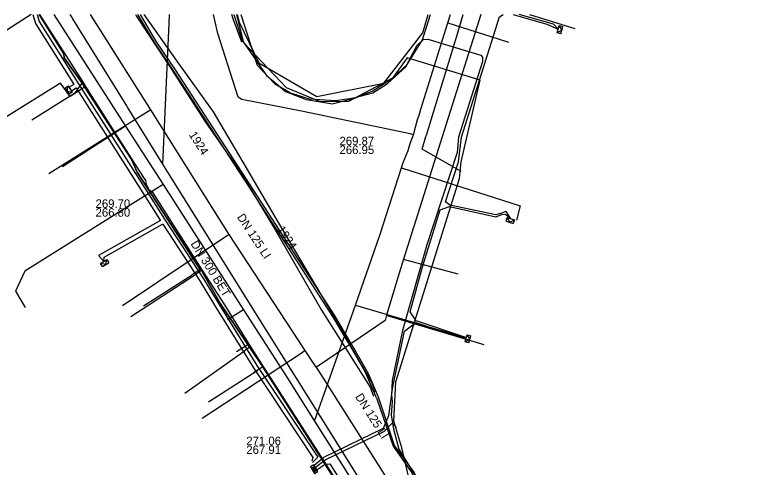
# Model space of a CAD drawing. Extents: x -600391 to -599491, y -1160176 to -1159402.
# Drawn here: x -600036.7 to -599967.6, y -1159444.5 to -1159401.8 of the extents above; entities that cross this region are included whole.
import ezdxf

# ---------------------------------------------------------------- set-up
doc = ezdxf.new("R2010")
doc.units = 0
for name, color, linetype in [('28', 7, 'Continuous'), ('31', 7, 'Continuous'), ('CETIN_linie', 7, 'Continuous'), ('UPC_ok_linie', 7, 'Continuous'), ('Vrstva 12', 7, 'Continuous'), ('Vrstva 13', 7, 'Continuous'), ('Vrstva 15', 7, 'Continuous'), ('Vrstva 16', 7, 'Continuous'), ('Vrstva 42', 7, 'Continuous'), ('Vrstva 43', 7, 'Continuous'), ('Vrstva 44', 7, 'Continuous'), ('Vrstva 55', 7, 'Continuous'), ('Vrstva 9', 7, 'Continuous')]:
    doc.layers.add(name, color=color, linetype=linetype)

# ---------------------------------------------------------------- blocks, each defined once
blk = doc.blocks.new('NN630')
at = {"layer": '31'}
for points in [[(0, -0.7), (-0.7, 0)], [(-0.7, -0.7), (-0.7, 0), (0.7, 0), (0.7, -0.7)], [(-0.7, -0.7), (0.7, -0.7)], [(0, -0.7), (0.7, 0)]]:
    blk.add_lwpolyline(points, dxfattribs=at)
blk = doc.blocks.new('NN620')
at = {"layer": '28'}
for points in [[(0.75, 0), (-0.75, 0)], [(-0.75, 0), (-0.75, -0.75)], [(0.75, -0.75), (0.75, 0)], [(-0.75, -0.75), (0.75, -0.75)], [(0.37, -0.18), (-0.38, -0.18)], [(-0.38, -0.18), (-0.38, -0.56)], [(-0.38, -0.56), (0.37, -0.56)], [(0.32, -0.23), (-0.33, -0.23)], [(-0.33, -0.23), (-0.33, -0.51)], [(-0.33, -0.51), (0.32, -0.51)], [(0.27, -0.27), (-0.28, -0.27)], [(-0.28, -0.27), (-0.28, -0.46)], [(-0.28, -0.46), (0.27, -0.46)], [(0.23, -0.32), (-0.23, -0.32)], [(-0.23, -0.32), (-0.23, -0.42)], [(-0.23, -0.42), (0.23, -0.42)], [(-0.19, -0.37), (0.19, -0.37)], [(0.23, -0.42), (0.23, -0.32)], [(0.27, -0.46), (0.27, -0.27)], [(0.32, -0.51), (0.32, -0.23)], [(0.37, -0.56), (0.37, -0.18)]]:
    blk.add_lwpolyline(points, dxfattribs=at)

msp = doc.modelspace()

# ---------------------------------------------------------------- linework, layer by layer
at = {"layer": 'CETIN_linie'}
for points in [[(-600034.364, -1159401.769), (-600030.328, -1159408.074), (-600030.031, -1159408.562), (-600027.154, -1159413.117), (-600024.979, -1159416.513), (-600024.37, -1159417.443), (-600024.306, -1159417.829), (-600024.061, -1159418.272), (-600023.747, -1159418.499), (-600019.056, -1159425.858), (-600016.92, -1159429.193), (-600014.446, -1159433.158), (-600001.116, -1159453.971)], [(-600030.031, -1159408.562), (-600030.786, -1159409.07), (-600031.492, -1159409.487), (-600032.4, -1159408.246), (-600037.636, -1159411.528)], [(-600019.056, -1159425.858), (-600019.736, -1159426.407), (-600025.751, -1159430.302)], [(-600014.603, -1159432.894), (-600015.786, -1159433.631)], [(-600014.446, -1159433.158), (-600014.773, -1159433.336), (-600015.141, -1159433.636), (-600020.665, -1159437.549)]]:
    msp.add_lwpolyline(points, dxfattribs=at)
at = {"layer": 'UPC_ok_linie'}
for p, q in [((-600035.09, -1159411.697), (-600030.98, -1159409.13)), ((-600024.574, -1159429.279), (-600019.96, -1159426.36)), ((-600018.423, -1159438.339), (-600013.77, -1159435.34))]:
    msp.add_line(p, q, dxfattribs=at)
for points in [[(-599993.41, -1159473.42), (-599991.88, -1159471.77), (-599991.41, -1159469.39), (-599997.86, -1159459.27), (-600001.08, -1159454.16), (-600013.3, -1159435.04), (-600017.28, -1159429.1), (-600019.04, -1159425.99), (-600019.22, -1159425.83), (-600025.16, -1159416.64), (-600025.73, -1159415.39), (-600030.34, -1159408.23), (-600032.04, -1159405.85), (-600032.07, -1159405.47), (-600034.395, -1159401.769)], [(-600034.395, -1159401.769), (-600032.07, -1159405.47), (-600032.04, -1159405.85), (-600030.34, -1159408.23)], [(-600015.283, -1159404.364), (-600016.11, -1159402.18), (-600016.222, -1159401.769)], [(-600030.34, -1159408.23), (-600025.73, -1159415.39), (-600025.16, -1159416.64), (-600019.22, -1159425.83), (-600019.04, -1159425.99), (-600017.28, -1159429.1), (-600013.3, -1159435.04), (-600001.08, -1159454.16), (-599997.86, -1159459.27), (-599991.41, -1159469.39), (-599991.88, -1159471.77), (-599993.41, -1159473.42), (-600006.88, -1159475.93), (-600026.86, -1159479.57), (-600031.58, -1159480.42), (-600034.09, -1159480.85), (-600059.85, -1159486.24), (-600064.94, -1159487.53), (-600069.33, -1159488.8), (-600073.81, -1159490), (-600078.56, -1159491.24), (-600078.73, -1159490.66)], [(-600030.98, -1159409.13), (-600030.34, -1159408.23)], [(-600019.22, -1159425.83), (-600019.96, -1159426.36)], [(-600013.3, -1159435.04), (-600014.19, -1159435.61)]]:
    msp.add_lwpolyline(points, dxfattribs=at)
at = {"layer": 'Vrstva 13'}
for p, q in [((-599988.114, -1159401.769), (-599983.845, -1159403.072)), ((-600008.253, -1159435.071), (-600008.449, -1159434.771)), ((-600007.959, -1159434.869), (-600008.253, -1159435.071)), ((-600008.253, -1159435.071), (-600008.026, -1159435.421))]:
    msp.add_line(p, q, dxfattribs=at)
for points in [[(-600017.912, -1159420.246), (-600023.882, -1159410.77), (-600029.572, -1159401.769)], [(-599992.718, -1159401.769), (-600000.021, -1159424.863), (-600000.41, -1159426.18), (-600001.607, -1159430.166), (-600001.753, -1159430.673), (-600007.959, -1159434.869)], [(-600023.882, -1159410.77), (-600027.38, -1159412.97), (-600033.51, -1159416.821)], [(-600008.449, -1159434.771), (-600009.314, -1159433.489), (-600016.467, -1159422.532), (-600017.912, -1159420.246)], [(-600016.467, -1159422.532), (-600016.62, -1159422.64), (-600026.551, -1159429.268)], [(-600000.021, -1159424.863), (-599999.917, -1159424.887), (-599994.881, -1159426.244)], [(-600001.607, -1159430.166), (-600001.45, -1159430.21), (-599992.421, -1159432.914)], [(-600009.314, -1159433.489), (-600009.69, -1159433.76), (-600019.007, -1159439.919)], [(-600008.026, -1159435.421), (-599994.308, -1159457.05), (-599989.477, -1159465.256), (-599989.215, -1159465.697)]]:
    msp.add_lwpolyline(points, dxfattribs=at)
at = {"layer": 'Vrstva 16'}
msp.add_line((-600035.165, -1159401.769), (-600039.67, -1159404.66), dxfattribs=at)
for points in [[(-600033.012, -1159401.769), (-600026.25, -1159412.31), (-600022.71, -1159417.82), (-600015.12, -1159429.64), (-600010.98, -1159436.1), (-600008.42, -1159440.16), (-600001.28, -1159451.47), (-599993, -1159464.59), (-599990.81, -1159468.06), (-599986.46, -1159474.93)], [(-599999.079, -1159413.111), (-599999.38, -1159413.03), (-600009.65, -1159410.9), (-600015.28, -1159409.8), (-600015.63, -1159409.58), (-600017.53, -1159403.54), (-600017.96, -1159401.769)], [(-599998.38, -1159410.69), (-599995.83, -1159402.53), (-599995.586, -1159401.769)], [(-599995.83, -1159402.53), (-599991.77, -1159403.85), (-599990.11, -1159404.36)], [(-599998.54, -1159411.25), (-599998.48, -1159411.04), (-599998.38, -1159410.69)], [(-599999.468, -1159414.242), (-599999.36, -1159413.86), (-599999.079, -1159413.111), (-599998.68, -1159411.66), (-599998.541, -1159411.254), (-599998.54, -1159411.25)], [(-600026.25, -1159412.31), (-600032.21, -1159416.13)], [(-600000.043, -1159415.725), (-599999.73, -1159414.98), (-599999.585, -1159414.61), (-599999.468, -1159414.242)], [(-600008.42, -1159440.16), (-600004.56, -1159429.2), (-600002.21, -1159422.5), (-600000.21, -1159416.25), (-600000.043, -1159415.725)], [(-600000.21, -1159416.25), (-599989, -1159419.83), (-599989.36, -1159421.18)], [(-600022.71, -1159417.82), (-600035.75, -1159426), (-600036.63, -1159427.88), (-600035.72, -1159429.43)], [(-600004.56, -1159429.2), (-599994.09, -1159432.3)], [(-600015.12, -1159429.64), (-600016.62, -1159430.601)]]:
    msp.add_lwpolyline(points, dxfattribs=at)
at = {"layer": 'Vrstva 42'}
for points in [[(-600034.998, -1159401.769), (-600034.754, -1159402.609), (-600031.489, -1159407.817), (-600031.146, -1159408.355), (-600031.583, -1159408.63), (-600031.476, -1159408.799), (-600031.37, -1159408.968), (-600030.932, -1159408.692), (-600022.988, -1159421.167), (-600022.952, -1159421.223), (-600028.813, -1159424.508), (-600028.31, -1159425.08), (-600028.287, -1159424.672), (-600022.762, -1159421.574), (-600022.735, -1159421.559), (-600019.24, -1159426.92), (-600017.764, -1159429.368), (-600014.184, -1159435.135), (-600008.572, -1159443.594), (-600008.678, -1159443.94)], [(-600034.609, -1159401.769), (-600034.406, -1159402.411), (-600031.151, -1159407.603), (-600022.514, -1159421.167), (-600018.902, -1159426.708), (-600017.422, -1159429.16), (-600013.848, -1159434.919), (-600008.111, -1159443.564), (-600008.593, -1159444.076)], [(-600015.728, -1159401.769), (-600015.529, -1159402.49), (-600013.667, -1159406.317), (-600008.209, -1159409.513), (-600001.882, -1159408.227), (-599998.205, -1159403.489), (-599997.695, -1159401.769)], [(-600015.382, -1159401.769), (-600013.831, -1159406.546), (-600012.2, -1159408.26), (-600010.69, -1159409.15), (-600008.93, -1159409.72), (-600006.4, -1159409.89), (-600004.7, -1159409.63), (-600002.9, -1159409.15), (-600001.54, -1159408.28), (-599999.81, -1159406.71), (-599998.74, -1159404.66), (-599998.14, -1159404.12), (-599997.71, -1159404.1), (-599992.73, -1159405.61), (-599992.546, -1159405.787), (-599992.561, -1159406.185), (-599994.836, -1159413.354), (-599994.956, -1159414.781), (-599997.801, -1159423.517), (-600000.11, -1159431.601), (-600000.47, -1159433.268), (-600001.093, -1159436.319), (-600001.15, -1159437.71), (-600001.08, -1159438.309), (-600001.17, -1159439.56), (-600000.97, -1159440.91), (-600000.46, -1159442.81), (-599995.03, -1159451.63)], [(-600008.441, -1159444.321), (-600007.538, -1159443.57), (-600001.906, -1159440.836), (-600001.385, -1159439.63), (-600001.037, -1159436.919), (-599999.922, -1159431.654), (-599998.86, -1159430.838), (-599994.19, -1159432.403), (-599994.094, -1159432.338), (-599994.145, -1159432.25), (-599998.81, -1159430.686), (-599999.378, -1159429.843), (-599998.234, -1159425.584), (-599996.557, -1159420.217), (-599995.676, -1159419.906), (-599991.287, -1159420.852), (-599990.725, -1159420.662), (-599990.388, -1159420.616), (-599989.884, -1159421.047), (-599990.334, -1159420.365), (-599990.775, -1159420.51), (-599991.297, -1159420.686), (-599995.642, -1159419.75), (-599996.049, -1159419.449), (-599994.828, -1159415.682), (-599994.541, -1159413.338), (-599990.961, -1159401.982), (-599990.593, -1159401.769)], [(-599989.668, -1159401.769), (-599986.491, -1159402.661), (-599985.412, -1159403.143), (-599985.845, -1159402.685), (-599989.084, -1159401.769)], [(-600008.33, -1159444.5), (-600007.403, -1159443.829), (-600001.801, -1159441.116), (-600001.097, -1159440.343), (-600000.69, -1159440.76)], [(-600008.18, -1159444.74), (-600007.408, -1159444.231), (-600006.974, -1159444.204), (-600000.609, -1159454.278), (-599997.758, -1159458.609), (-599990.268, -1159469.922), (-599992.891, -1159473.659), (-599990.704, -1159479.258), (-599990.564, -1159479.538), (-599987.939, -1159479.206), (-599984.884, -1159480.262), (-599983.88, -1159481.7), (-599975.77, -1159494.52), (-599968.566, -1159505.921), (-599969.518, -1159509.505), (-599970.644, -1159513.194), (-599971.636, -1159515.78), (-599972.232, -1159515.683)]]:
    msp.add_lwpolyline(points, dxfattribs=at)
at = {"layer": 'Vrstva 44'}
for points in [[(-600025.312, -1159401.769), (-600025.24, -1159401.87), (-600021.95, -1159406.89), (-600018.72, -1159411.92), (-600015.31, -1159416.8), (-600012.17, -1159422.02), (-600007.76, -1159429.69), (-600003.17, -1159436.95), (-600002.838, -1159437.797)], [(-600002.569, -1159437.968), (-600003.467, -1159435.852), (-600003.804, -1159435.217), (-600005.213, -1159432.779), (-600006.692, -1159430.271), (-600014.65, -1159417.953), (-600021.71, -1159407.104), (-600023.561, -1159404.342), (-600025.088, -1159401.769)], [(-600002.385, -1159437.89), (-600003.286, -1159435.766), (-600003.629, -1159435.12), (-600005.04, -1159432.678), (-600006.521, -1159430.166), (-600014.483, -1159417.844), (-600021.543, -1159406.994), (-600023.392, -1159404.235), (-600024.855, -1159401.769)], [(-600002.658, -1159437.433), (-600002.96, -1159436.59), (-600007.2, -1159429.2), (-600011.81, -1159421.41), (-600014.84, -1159416.23), (-600017.94, -1159410.96), (-600021.38, -1159406.16), (-600024.505, -1159401.769)], [(-600002.569, -1159437.968), (-600000.98, -1159442.54), (-599999.22, -1159445.04), (-599998.3, -1159447.13), (-599990.28, -1159460), (-599987.96, -1159464), (-599982.62, -1159471.51), (-599973.11, -1159470.39), (-599963.06, -1159468.74), (-599957.24, -1159468.52), (-599955.54, -1159469.04), (-599946.72, -1159471.99), (-599945.19, -1159473.11), (-599945.49, -1159474.29)], [(-599955.67, -1159465.18), (-599956.36, -1159467.68), (-599957.15, -1159468.24), (-599963.11, -1159468.61), (-599972.99, -1159470.17), (-599982.65, -1159471.3), (-599987.79, -1159463.88), (-599990.03, -1159459.92), (-599998.15, -1159447.02), (-599999.01, -1159444.97), (-600000.86, -1159442.46), (-600002.385, -1159437.89)]]:
    msp.add_lwpolyline(points, dxfattribs=at)
at = {"layer": 'Vrstva 55'}
for points in [[(-600016.021, -1159401.769), (-600015.348, -1159403.902), (-600015.27, -1159404.15), (-600012.94, -1159407.52), (-600011.89, -1159408.4), (-600011.15, -1159409.04), (-600009.19, -1159409.77), (-600006.92, -1159410.17), (-600006.75, -1159410.18)], [(-599992.62, -1159470.37), (-599985.75, -1159466.87), (-599999.406, -1159445.91), (-600000.16, -1159442.69), (-600000.92, -1159440.18), (-600000.73, -1159436.44), (-599994.74, -1159417.25), (-599994.56, -1159415.68), (-599992.79, -1159407.97), (-599999.66, -1159405.86), (-600001.05, -1159407.76), (-600005.22, -1159409.97), (-600007.84, -1159409.99), (-600011.06, -1159408.67), (-600015.09, -1159404.42), (-600015.756, -1159401.769)], [(-600006.75, -1159410.18), (-600004.64, -1159409.67), (-600002.97, -1159408.99), (-600001.05, -1159407.76), (-599999.66, -1159406.47), (-599998.22, -1159404.16), (-599997.467, -1159401.769)]]:
    msp.add_lwpolyline(points, dxfattribs=at)
at = {"layer": 'Vrstva 9'}
msp.add_line((-599994.57, -1159416.583), (-599998.26, -1159414.48), dxfattribs=at)
for points in [[(-600022.74, -1159415.89), (-600026.062, -1159410.502), (-600026.128, -1159410.394), (-600031.224, -1159402.171), (-600031.296, -1159402.055), (-600031.473, -1159401.769)], [(-600022.74, -1159415.89), (-600022.151, -1159402.58), (-600022.115, -1159401.769)], [(-599998.26, -1159414.48), (-599997.898, -1159413.294), (-599997.851, -1159413.141), (-599997.194, -1159410.99), (-599995.028, -1159403.892), (-599994.38, -1159401.769)], [(-600006.69, -1159441.58), (-600013.816, -1159430.173), (-600013.975, -1159429.919), (-600021.944, -1159417.163), (-600022.74, -1159415.89)], [(-599988.43, -1159470.91), (-599994.08, -1159461.835), (-599998.414, -1159454.874), (-599998.953, -1159454.008), (-600006.69, -1159441.58)]]:
    msp.add_lwpolyline(points, dxfattribs=at)

# ---------------------------------------------------------------- block references
at = {"layer": 'Vrstva 43'}
for name, p, xscale, yscale, rotation in [('NN630', (-599985.412, -1159403.142), 0.5, 0.5000000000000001, 75), ('NN630', (-600031.476, -1159408.799), 0.5, 0.5, -57.00000000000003), ('NN630', (-599989.884, -1159421.047), 0.5000000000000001, 0.5, -17.000000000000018), ('NN630', (-600028.31, -1159425.08), 0.5, 0.5, 31), ('NN630', (-599994.094, -1159432.338), 0.5, 0.5000000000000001, 73), ('NN620', (-600008.292, -1159444.607), 0.49999999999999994, 0.5000000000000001, -58.00000000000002)]:
    msp.add_blockref(name, p, dxfattribs=dict(at, xscale=xscale, yscale=yscale, rotation=rotation))

# ---------------------------------------------------------------- texts
at = {"layer": 'Vrstva 12'}
for s, p in [('269.87', (-600006.056, -1159414.103)), ('266.95', (-600006.056, -1159414.935)), ('269.70', (-600029.085, -1159420.019)), ('266.80', (-600029.085, -1159420.851)), ('271.06', (-600014.855, -1159442.43)), ('267.91', (-600014.855, -1159443.262))]:
    msp.add_text(s, height=0.8, dxfattribs=at).set_placement(p)
msp.add_text('DN 300 BET', height=0.8, rotation=302.00891, dxfattribs=at).set_placement((-600020.147, -1159423.415))
at = {"layer": 'Vrstva 15'}
for s, rotation, p in [('1924', 302.34562, (-600020.305, -1159413.109)), ('DN 125 LI', 303.15196, (-600015.764, -1159420.893)), ('1924', 303.15196, (-600011.996, -1159422.051)), ('DN 125 LI', 302.40712, (-600004.613, -1159437.853))]:
    msp.add_text(s, height=0.8, rotation=rotation, dxfattribs=at).set_placement(p)

doc.saveas('drawing.dxf')
